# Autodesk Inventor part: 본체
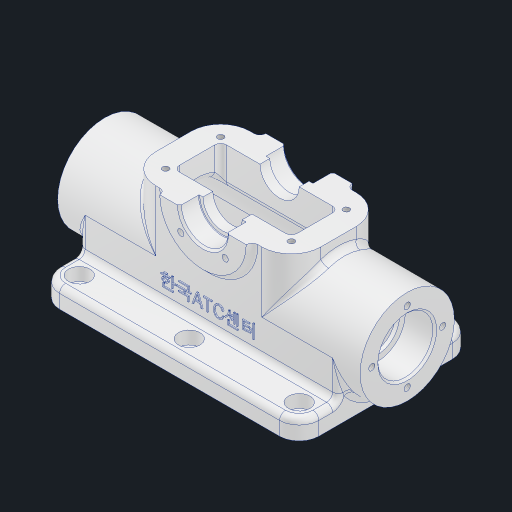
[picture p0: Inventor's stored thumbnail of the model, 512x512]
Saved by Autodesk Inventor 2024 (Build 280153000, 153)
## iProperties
Created: 2024-06
Part Number: 본체
Material: 알루미늄 6061
Document SubType Name: Modeling
Designer: kh_501
Density: 2.7 g/cm^3
Appearance: 알루미늄 - 평지
Mass: 553.392 g
Surface Area: 604.003 cm^2
Volume: 204.96 cm^3
Author: kh_501
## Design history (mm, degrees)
sketch "스케치1"
  geometry: L1 (-77, 0)-(77, 0); L2 (-77, 24)-(77, 24); L3 (77, 24)-(77, 14); L4 (77, 14)-(62, 14); L5 (62, 14)-(62, 11); L6 (62, 11)-(60, 11); L7 (60, 11)-(60, 0); L8 (60, 0)-(-60, 0); L9 (-60, 0)-(-60, 11); L10 (-60, 11)-(-62, 11); L11 (-62, 11)-(-62, 14); L12 (-62, 14)-(-77, 14); L13 (-77, 14)-(-77, 24); 4 further points
  constraints: 26 end point, 8 perpendicular, 6 point on line, 2 horizontal, 1 coincident, 1 collinear, 1 midpoint, 1 vertical
  dimensions: "d0" = 154 distance of L1.start L1.end; "d1" = 48 diameter of L2 L1; "d2" = 28 diameter of L4 L1; "d3" = 22 diameter of L6 L1; "d4" = 15 distance between parallel lines of L5 L3; "d5" = 15 distance of L11.end L12.end; "d6" = 120 distance between parallel lines of L9 L7; "d7" = 60 distance of L7.end point (0, 0) (= 0.5 x d6)
revolve "회전1" sketch "스케치1" stored, may be unused: angle "d8" = 90 deg
node "작업 평면1"
node "작업 평면2"
sketch "스케치3"
  geometry: L1 (66, -44)-(-66, -44); L2 (-66, -44)-(-66, 44); L3 (-66, 44)-(66, 44); L4 (66, 44)-(66, -44); 3 further points
  constraints: 8 end point, 2 midpoint, 2 parallel, 1 horizontal, 1 horizontal alignment, 1 perpendicular, 1 vertical alignment
  dimensions: "d12" = 88 distance of L1.end L2.end; "d13" = 132 distance between parallel lines of L4 L2
extrude "돌출1" join sketch "스케치3" distance "d14" = 10; taper "d15" = 0 deg
sketch "스케치2"
  geometry: L1 (42, -24)-(-42, -24); L2 (-42, -24)-(-42, 24); L3 (-42, 24)-(42, 24); L4 (42, 24)-(42, -24); L5 (-77, -24)-(77, -24) reference; L6 (-77, 24)-(77, 24) reference; 2 further points
  constraints: 8 end point, 2 collinear, 2 parallel, 1 horizontal, 1 midpoint, 1 perpendicular, 1 vertical alignment
  dimensions: "d10" = 84 distance between parallel lines of L4 L2
extrude "돌출2" join sketch "스케치2" stored distance "d16" = 10; taper "d17" = 0 deg
sketch "스케치4"
  geometry: L1 (-42, -24)-(-42, -15.875) reference; L2 (-66, -15.875)-(-42, -15.875) reference; L3 (-66, -15.875)-(-66, -44) reference; L4 (-66, -44)-(66, -44) reference; L5 (66, -44)-(66, -15.875) reference; L6 (42, -15.875)-(66, -15.875) reference; L7 (42, -15.875)-(42, -24) reference; L8 (42, -24)-(-42, -24) reference; L9 (42, -24)-(66, -24); L10 (-42, -24)-(-66, -24); L11 (-42, 24)-(42, 24) reference; L12 (-42, 15.875)-(-42, 24) reference; L13 (-42, 24)-(42, 24) reference; L14 (42, 24)-(42, 15.875) reference; L15 (66, 15.875)-(42, 15.875) reference; L16 (66, 15.875)-(66, 44) reference; L17 (66, 44)-(-66, 44) reference; L18 (-66, 44)-(-66, 15.875) reference; L19 (-42, 15.875)-(-66, 15.875) reference; L20 (-42, 24)-(-66, 24); L21 (42, 24)-(66, 24); 1 further point
  constraints: 8 end point, 5 point on line, 2 perpendicular, 1 horizontal
extrude "돌출3" join sketch "스케치4" stored distance "d18" = 10; taper "d19" = 0 deg
sketch "스케치6"
  geometry: L1 (0, 27)-(0, -27); L2 (0, 27)-(22, 27); L3 (22, 27)-(22, -27); L4 (22, -27)-(0, -27); 2 further points
  constraints: 8 end point, 2 perpendicular, 1 coincident, 1 horizontal, 1 midpoint, 1 vertical
  dimensions: "d23" = 54 distance of L1.start L1.end; "d24" = 44 diameter of L3 L1
revolve "회전2" sketch "스케치6" stored, may be unused: angle "d25" = 180 deg
sketch "스케치7"
  geometry: L1 (31, -24)-(31, 24) reference; L2 (31, 32.555)-(31, -31.32); L3 (9, 27)-(31, 27) reference; L4 (9, -27)-(31, -27) reference; L5 (19, 27)-(19, 17); L6 (19, 17)-(21, 17); L7 (21, 17)-(21, -17); L8 (21, -17)-(19, -17); L9 (19, -17)-(19, -27); 3 further points
  constraints: 12 end point, 4 point on line, 3 perpendicular, 2 vertical, 1 collinear
  dimensions: "d27" = 24 diameter of L9 L2; "d28" = 20 diameter of L7 L2; "d29" = 10 distance of L8.end L9.end; "d30" = 10 distance of L5.start L5.end
revolve "회전3" sketch "스케치7" stored, may be unused: angle "d31" = 360 deg
sketch "스케치5"
  geometry: L1 (0, -18)-(-28, -18); L2 (-28, -18)-(-28, 18); L3 (-28, 18)-(0, 18); L4 (-28, -44)-(-28, 44) reference; L5 (-18, 24)-(0, 24) reference; A1 r 18 centre (0, 0) between (0, -18) and (0, 18); 1 further point
  constraints: 6 end point, 2 coincident, 2 point on circle, 2 tangent, 1 centre point, 1 collinear, 1 horizontal, 1 parallel, 1 perpendicular
  dimensions: "d20" = 6 distance between parallel lines of L5 L3
extrude "돌출5" cut sketch "스케치5" stored distance "d32" = 120; taper "d33" = 0 deg
sketch "스케치8"
  geometry: L1 (30, -12)-(-30, -12); L2 (-30, -12)-(-30, 12); L3 (-30, 12)-(30, 12); L4 (30, 12)-(30, -12); L5 (30, -12)-(-30, 12); L6 (-30, -12)-(30, 12); 1 further point
  constraints: 12 end point, 2 midpoint, 2 parallel, 1 horizontal, 1 perpendicular
  dimensions: "d34" = 60 distance between parallel lines of L2 L4; "d35" = 24 distance of L3.end L1.start
extrude "돌출6" cut sketch "스케치8" stored distance "d36" = 120; taper "d37" = 0 deg
fillet "모깎기1" dims "d38" = 10
sketch "스케치9"
  geometry: A1 r 10 centre (-56, 34) between (-56, 44) and (-66, 34) reference; A2 r 10 centre (56, 34) between (66, 34) and (56, 44) reference; A3 r 10 centre (56, -34) between (56, -44) and (66, -34) reference; A4 r 10 centre (-56, -34) between (-66, -34) and (-56, -44) reference; 7 further points
  constraints: 4 coincident, 2 horizontal alignment, 2 vertical alignment
hole "구멍1" sketch "스케치9" at (-56, 34), (56, 34), (56, -34), (-56, -34), (0, 34), (0, -34) diameter "d39" = 6.6; stored, may be unused: countersink angle "d43" = 82 deg, drill point angle "d45" = 0 deg; dims "d40" = 6, "d41" = 11, "d42" = 6.6, "d44" = 8
sketch "스케치10"
  geometry: L1 (32, -14)-(-32, -14); L2 (-32, -14)-(-32, 14); L3 (-32, 14)-(32, 14); L4 (32, 14)-(32, -14); L5 (32, -14)-(-32, 14); L6 (-32, -14)-(32, 14); 5 further points
  constraints: 12 end point, 4 coincident, 2 midpoint, 2 parallel, 1 horizontal, 1 perpendicular
  dimensions: "d46" = 64 distance of L2.end L3.end; "d47" = 28 distance of L3.end L1.start
hole "구멍2" sketch "스케치10" at (-32, 14), (-32, -14), (32, 14), (32, -14) diameter "d48" = 3.242; stored, may be unused: countersink angle "d52" = 90 deg, drill point angle "d54" = 118 deg; dims "d49" = 8, "d50" = 11, "d51" = 6.6, "d53" = 10
sketch "스케치11"
  geometry: L1 (0, 0)-(-11.314, -11.314); L2 (0, 0)-(0, -31); L3 (0, 0)-(11.314, -11.314); A1 r 12 centre (0, 0) between (-12, 0) and (12, 0) reference; A2 r 16 centre (0, 0) between (-11.314, -11.314) and (11.314, -11.314); 2 further points
  constraints: 6 end point, 3 coincident, 2 point on circle, 1 centre point, 1 vertical
  dimensions: "d55" = 32 diameter of A2; "d56" = 45 deg angle of L1 L2; "d57" = 45 deg angle of L2 L3
hole "구멍3" sketch "스케치11" at (-11.314, -11.314), (11.314, -11.314) diameter "d58" = 3.242; stored, may be unused: countersink angle "d62" = 90 deg, drill point angle "d64" = 118 deg; dims "d59" = 8, "d60" = 4, "d61" = 2, "d63" = 10
sketch "스케치13" dims "d81" = 36
  geometry: 3 further points
  constraints: 2 vertical alignment, 1 coincident, 2 other
hole "구멍4" sketch "스케치13" at (0, 18) diameter "d82" = 3.242; stored, may be unused: countersink angle "d86" = 90 deg, drill point angle "d88" = 118 deg; dims "d83" = 8, "d84" = 4, "d85" = 2, "d87" = 10
fillet "모깎기2" dims "d65" = 0.3
fillet "모깎기3" dims "d66" = 15
fillet "모깎기4" dims "d67" = 3
fillet "모깎기5" dims "d68" = 3
fillet "모깎기6" dims "d69" = 3
fillet "모깎기7" dims "d70" = 3
sketch "스케치12" dims "d0" = 154
  geometry: L1 (-56, -59)-(56, -59) reference; 2 further points
  constraints: 1 vertical alignment, 1 other
  dimensions: "d71" = 20 distance from line of L1 point (0, -39)
feature "엠보싱1" sketch "스케치12" dims "d0" = 154, "d1" = 48, "d2" = 28, "d3" = 22, "d4" = 15, "d5" = 15, "d6" = 120, "d7" = 60 (= 0.5 x d6), "d10" = 84, "d72" = 0.5, "d73" = 0
fillet "모깎기8" dims "d74" = 3
fillet "모깎기9" dims "d75" = 3
fillet "모깎기10" dims "d76" = 3
chamfer "모따기1" distance "d77" = 1; stored, may be unused: second distance "d78" = 2, angle "d79" = 45 deg
fillet "모깎기11" dims "d80" = 3
node "솔리드1"
mirror "미러1"
pattern_circular "원형 패턴1" dims angle "d90" = 360 deg
mirror "미러2"
node "투영된 루프1"
node "투영된 루프2"
feature "A9D066F2-1C7D-4E18-AEED-F7BC21143FA4" dims "d39" = 6.6, "d40" = 6, "d41" = 11, "d42" = 6.6, "d43" = 82 deg, "d44" = 8, "d45" = 0
other parameters: "d9" = 31, "d11" = -28
